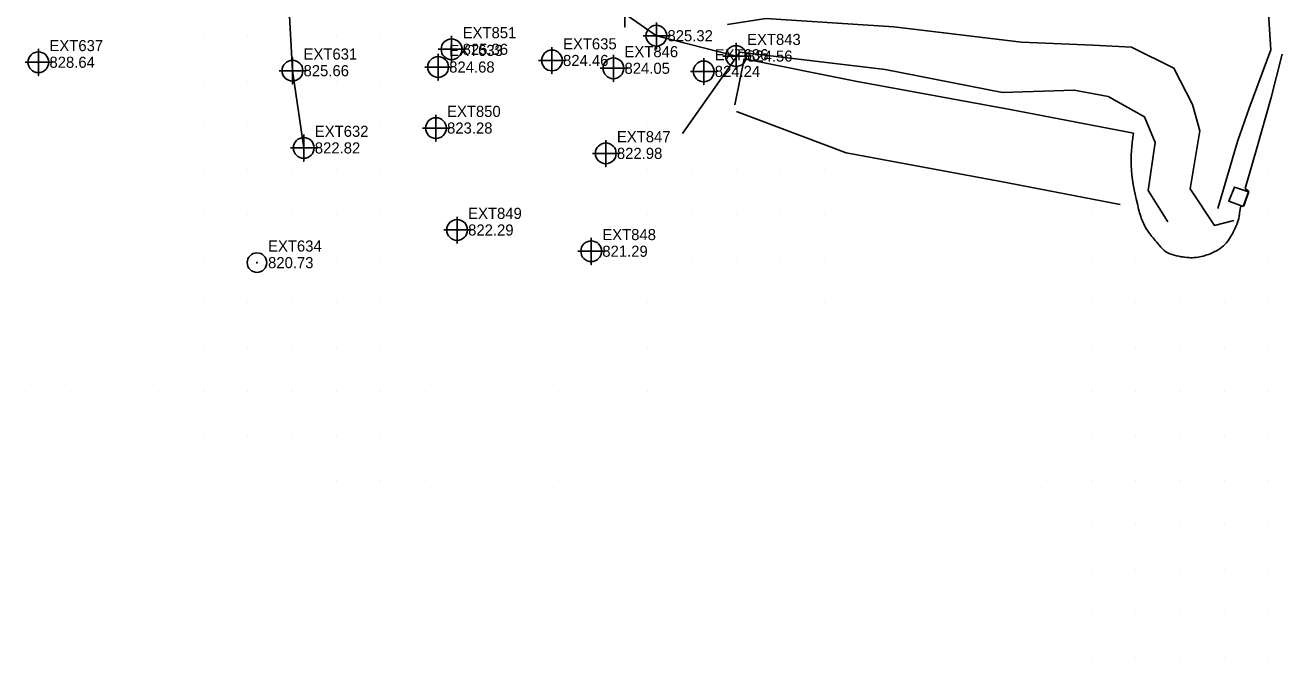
# Model space of a CAD drawing. Extents: x 1762120 to 1766775, y 709485 to 712965.
# Drawn here: x 1762809.9 to 1763091.8, y 712400 to 712542.6 of the extents above; entities that cross this region are included whole.
import ezdxf

# ---------------------------------------------------------------- set-up
doc = ezdxf.new("R2010")
doc.units = 0
for name, color, linetype in [('Exist DTM Breakline', 7, 'Continuous'), ('Exist DTM Breakline Cogo Elevation', 7, 'Continuous'), ('Exist DTM Breakline Cogo Number', 7, 'Continuous'), ('Exist DTM Breakline Cogo Point CELL', 7, 'Continuous'), ('Exist DTM QL2 LIDAR Elevation Point', 7, 'Continuous'), ('Exist DTM Regular Point CELL', 7, 'Continuous'), ('Exist DTM Regular Point Cogo Elevation', 7, 'Continuous'), ('Exist DTM Regular Point Cogo Number', 7, 'Continuous'), ('Exist Property Iron Pin CELL', 7, 'Continuous'), ('Exist Property Iron Pin Cogo Elevation', 7, 'Continuous'), ('Exist Property Iron Pin Cogo Number', 7, 'Continuous'), ('Exist Roads EOP', 7, 'Continuous'), ('Exist Roads EOP Other', 7, 'Continuous')]:
    doc.layers.add(name, color=color, linetype=linetype)

msp = doc.modelspace()

# ---------------------------------------------------------------- linework, layer by layer
at = {"layer": 'Exist DTM Breakline'}
for points in [[(1763078.51, 712501.3), (1763082.89, 712516.4), (1763085.56, 712523.9), (1763090.42, 712537.05), (1763089.79, 712546.34), (1763082.89, 712551.55), (1763067.24, 712555.92), (1763059.84, 712556.24), (1763056.72, 712558.52), (1763053.11, 712557.11), (1763041.81, 712560.64), (1763027.13, 712563.07), (1763013.63, 712566.46), (1762998, 712571.18), (1762987.84, 712574.31), (1762976.14, 712576.14), (1762969.55, 712578.67)], [(1762967.82, 712549.03), (1762948.14, 712552.08), (1762916.63, 712551.93), (1762895.25, 712554.12), (1762880.51, 712555.14), (1762869.37, 712546.08), (1762870.08, 712532.35), (1762872.62, 712514.94)], [(1762969.97, 712535.64), (1762952.03, 712540.23), (1762944.95, 712545.17)], [(1763082.1, 712498.57), (1763077.71, 712497.47), (1763072.23, 712505.75), (1763074.42, 712518.77), (1763072.8, 712524.74), (1763068.57, 712532.95), (1763059, 712537.64), (1763050.39, 712538.11), (1763034.3, 712538.76), (1763005.54, 712542.24), (1762976.69, 712544.08), (1762968.07, 712542.75), (1762968.07, 712542.75)], [(1762957.94, 712518.18), (1762970.82, 712536.53), (1763003.56, 712532.58), (1763029.97, 712527.47), (1763046.16, 712527.96), (1763053.81, 712526.52), (1763061.98, 712521.96), (1763064.38, 712516.19), (1763062.82, 712505.34), (1763067.21, 712498.31)], [(1762970.05, 712523.18), (1762994.75, 712513.87), (1763029.64, 712507.36), (1763056.49, 712502.17)]]:
    msp.add_lwpolyline(points, dxfattribs=at)
at = {"layer": 'Exist DTM Breakline Cogo Point CELL'}
for points in [[(1762944.95, 712548.17), (1762944.95, 712542.17), (1762944.95, 712545.17), (1762947.95, 712545.17), (1762941.95, 712545.17)], [(1762952.03, 712543.23), (1762952.03, 712537.23), (1762952.03, 712540.23), (1762955.03, 712540.23), (1762949.03, 712540.23)], [(1762969.97, 712538.64), (1762969.97, 712532.64), (1762969.97, 712535.64), (1762972.97, 712535.64), (1762966.97, 712535.64)], [(1762870.08, 712535.35), (1762870.08, 712529.35), (1762870.08, 712532.35), (1762873.08, 712532.35), (1762867.08, 712532.35)], [(1762872.62, 712517.94), (1762872.62, 712511.94), (1762872.62, 712514.94), (1762875.62, 712514.94), (1762869.62, 712514.94)]]:
    msp.add_lwpolyline(points, dxfattribs=at)
for centre in [(1762952.03, 712540.23), (1762969.97, 712535.64), (1762870.08, 712532.35), (1762872.62, 712514.94)]:
    msp.add_circle(centre, 2.34, dxfattribs=at)
at = {"layer": 'Exist DTM QL2 LIDAR Elevation Point'}
for p, q in [((1762810, 712540), (1762810, 712540)), ((1762820, 712540), (1762820, 712540)), ((1762830, 712540), (1762830, 712540)), ((1762840, 712540), (1762840, 712540)), ((1762850, 712540), (1762850, 712540)), ((1762860, 712540), (1762860, 712540)), ((1762880, 712540), (1762880, 712540)), ((1762890, 712540), (1762890, 712540)), ((1762900, 712540), (1762900, 712540)), ((1762810, 712530), (1762810, 712530)), ((1762820, 712530), (1762820, 712530)), ((1762830, 712530), (1762830, 712530)), ((1762840, 712530), (1762840, 712530)), ((1762850, 712530), (1762850, 712530)), ((1762860, 712530), (1762860, 712530)), ((1762880, 712530), (1762880, 712530)), ((1762890, 712530), (1762890, 712530)), ((1762900, 712530), (1762900, 712530)), ((1762810, 712520), (1762810, 712520)), ((1762820, 712520), (1762820, 712520)), ((1762830, 712520), (1762830, 712520)), ((1762840, 712520), (1762840, 712520)), ((1762850, 712520), (1762850, 712520)), ((1762860, 712520), (1762860, 712520)), ((1762880, 712520), (1762880, 712520)), ((1762890, 712520), (1762890, 712520)), ((1762950, 712520), (1762950, 712520)), ((1762810, 712510), (1762810, 712510)), ((1762820, 712510), (1762820, 712510)), ((1762830, 712510), (1762830, 712510)), ((1762840, 712510), (1762840, 712510)), ((1762850, 712510), (1762850, 712510)), ((1762860, 712510), (1762860, 712510)), ((1762870, 712510), (1762870, 712510)), ((1762880, 712510), (1762880, 712510)), ((1762890, 712510), (1762890, 712510)), ((1762950, 712510), (1762950, 712510)), ((1762960, 712510), (1762960, 712510)), ((1762970, 712510), (1762970, 712510)), ((1762980, 712510), (1762980, 712510)), ((1762990, 712510), (1762990, 712510)), ((1763090, 712510), (1763090, 712510)), ((1762810, 712500), (1762810, 712500)), ((1762820, 712500), (1762820, 712500)), ((1762830, 712500), (1762830, 712500)), ((1762840, 712500), (1762840, 712500)), ((1762850, 712500), (1762850, 712500)), ((1762860, 712500), (1762860, 712500)), ((1762870, 712500), (1762870, 712500)), ((1762880, 712500), (1762880, 712500)), ((1762890, 712500), (1762890, 712500)), ((1762950, 712500), (1762950, 712500)), ((1762960, 712500), (1762960, 712500)), ((1762970, 712500), (1762970, 712500)), ((1762980, 712500), (1762980, 712500)), ((1762990, 712500), (1762990, 712500)), ((1763000, 712500), (1763000, 712500)), ((1763010, 712500), (1763010, 712500)), ((1763020, 712500), (1763020, 712500)), ((1763030, 712500), (1763030, 712500)), ((1763040, 712500), (1763040, 712500)), ((1763050, 712500), (1763050, 712500)), ((1763090, 712500), (1763090, 712500)), ((1762810, 712490), (1762810, 712490)), ((1762820, 712490), (1762820, 712490)), ((1762830, 712490), (1762830, 712490)), ((1762840, 712490), (1762840, 712490)), ((1762850, 712490), (1762850, 712490)), ((1762860, 712490), (1762860, 712490)), ((1762870, 712490), (1762870, 712490)), ((1762880, 712490), (1762880, 712490)), ((1762890, 712490), (1762890, 712490)), ((1762950, 712490), (1762950, 712490)), ((1762960, 712490), (1762960, 712490)), ((1762970, 712490), (1762970, 712490)), ((1762980, 712490), (1762980, 712490)), ((1762990, 712490), (1762990, 712490)), ((1763000, 712490), (1763000, 712490)), ((1763010, 712490), (1763010, 712490)), ((1763020, 712490), (1763020, 712490)), ((1763030, 712490), (1763030, 712490)), ((1763040, 712490), (1763040, 712490)), ((1763050, 712490), (1763050, 712490)), ((1763060, 712490), (1763060, 712490)), ((1763090, 712490), (1763090, 712490)), ((1762810, 712480), (1762810, 712480)), ((1762820, 712480), (1762820, 712480)), ((1762830, 712480), (1762830, 712480)), ((1762840, 712480), (1762840, 712480)), ((1762850, 712480), (1762850, 712480)), ((1762860, 712480), (1762860, 712480)), ((1762870, 712480), (1762870, 712480)), ((1762880, 712480), (1762880, 712480)), ((1762890, 712480), (1762890, 712480)), ((1762900, 712480), (1762900, 712480)), ((1762910, 712480), (1762910, 712480)), ((1762920, 712480), (1762920, 712480)), ((1762930, 712480), (1762930, 712480)), ((1762940, 712480), (1762940, 712480)), ((1762950, 712480), (1762950, 712480)), ((1762990, 712480), (1762990, 712480)), ((1763000, 712480), (1763000, 712480)), ((1763010, 712480), (1763010, 712480)), ((1763020, 712480), (1763020, 712480)), ((1763030, 712480), (1763030, 712480)), ((1763040, 712480), (1763040, 712480)), ((1763050, 712480), (1763050, 712480)), ((1763060, 712480), (1763060, 712480)), ((1763070, 712480), (1763070, 712480)), ((1763080, 712480), (1763080, 712480)), ((1763090, 712480), (1763090, 712480)), ((1762810, 712470), (1762810, 712470)), ((1762820, 712470), (1762820, 712470)), ((1762830, 712470), (1762830, 712470)), ((1762840, 712470), (1762840, 712470)), ((1762850, 712470), (1762850, 712470)), ((1762860, 712470), (1762860, 712470)), ((1762870, 712470), (1762870, 712470)), ((1762880, 712470), (1762880, 712470)), ((1762890, 712470), (1762890, 712470)), ((1762900, 712470), (1762900, 712470)), ((1762910, 712470), (1762910, 712470)), ((1762920, 712470), (1762920, 712470)), ((1762930, 712470), (1762930, 712470)), ((1762940, 712470), (1762940, 712470)), ((1762950, 712470), (1762950, 712470)), ((1763030, 712470), (1763030, 712470)), ((1763040, 712470), (1763040, 712470)), ((1763050, 712470), (1763050, 712470)), ((1763060, 712470), (1763060, 712470)), ((1763070, 712470), (1763070, 712470)), ((1763080, 712470), (1763080, 712470)), ((1763090, 712470), (1763090, 712470)), ((1762810, 712460), (1762810, 712460)), ((1762820, 712460), (1762820, 712460)), ((1762830, 712460), (1762830, 712460)), ((1762840, 712460), (1762840, 712460)), ((1762850, 712460), (1762850, 712460)), ((1762860, 712460), (1762860, 712460)), ((1762870, 712460), (1762870, 712460)), ((1762880, 712460), (1762880, 712460)), ((1762890, 712460), (1762890, 712460)), ((1762900, 712460), (1762900, 712460)), ((1762910, 712460), (1762910, 712460)), ((1762920, 712460), (1762920, 712460)), ((1762930, 712460), (1762930, 712460)), ((1762940, 712460), (1762940, 712460)), ((1762950, 712460), (1762950, 712460)), ((1763050, 712460), (1763050, 712460)), ((1763060, 712460), (1763060, 712460)), ((1763070, 712460), (1763070, 712460)), ((1763080, 712460), (1763080, 712460)), ((1763090, 712460), (1763090, 712460)), ((1762840, 712450), (1762840, 712450)), ((1762850, 712450), (1762850, 712450)), ((1762860, 712450), (1762860, 712450)), ((1762870, 712450), (1762870, 712450)), ((1762880, 712450), (1762880, 712450)), ((1762890, 712450), (1762890, 712450)), ((1762900, 712450), (1762900, 712450)), ((1762910, 712450), (1762910, 712450)), ((1762920, 712450), (1762920, 712450)), ((1762930, 712450), (1762930, 712450)), ((1762940, 712450), (1762940, 712450)), ((1763040, 712450), (1763040, 712450)), ((1763050, 712450), (1763050, 712450)), ((1763060, 712450), (1763060, 712450)), ((1763070, 712450), (1763070, 712450)), ((1763080, 712450), (1763080, 712450)), ((1763090, 712450), (1763090, 712450)), ((1762880, 712440), (1762880, 712440)), ((1762890, 712440), (1762890, 712440)), ((1762900, 712440), (1762900, 712440)), ((1762910, 712440), (1762910, 712440)), ((1762920, 712440), (1762920, 712440)), ((1762930, 712440), (1762930, 712440)), ((1762940, 712440), (1762940, 712440)), ((1763040, 712440), (1763040, 712440)), ((1763050, 712440), (1763050, 712440)), ((1763060, 712440), (1763060, 712440)), ((1763070, 712440), (1763070, 712440)), ((1763080, 712440), (1763080, 712440)), ((1763090, 712440), (1763090, 712440)), ((1762930, 712430), (1762930, 712430)), ((1762940, 712430), (1762940, 712430)), ((1763040, 712430), (1763040, 712430)), ((1763050, 712430), (1763050, 712430)), ((1763060, 712430), (1763060, 712430)), ((1763070, 712430), (1763070, 712430)), ((1763080, 712430), (1763080, 712430)), ((1763090, 712430), (1763090, 712430)), ((1763040, 712420), (1763040, 712420)), ((1763050, 712420), (1763050, 712420)), ((1763060, 712420), (1763060, 712420)), ((1763070, 712420), (1763070, 712420)), ((1763080, 712420), (1763080, 712420)), ((1763090, 712420), (1763090, 712420)), ((1763040, 712410), (1763040, 712410)), ((1763050, 712410), (1763050, 712410)), ((1763060, 712410), (1763060, 712410)), ((1763070, 712410), (1763070, 712410)), ((1763080, 712410), (1763080, 712410)), ((1763090, 712410), (1763090, 712410)), ((1763040, 712400), (1763040, 712400)), ((1763050, 712400), (1763050, 712400)), ((1763060, 712400), (1763060, 712400)), ((1763070, 712400), (1763070, 712400)), ((1763080, 712400), (1763080, 712400)), ((1763090, 712400), (1763090, 712400))]:
    msp.add_line(p, q, dxfattribs=at)
at = {"layer": 'Exist DTM Regular Point CELL'}
for points in [[(1762905.91, 712540.17), (1762905.91, 712534.17), (1762905.91, 712537.17), (1762908.91, 712537.17), (1762902.91, 712537.17)], [(1762812.86, 712537.25), (1762812.86, 712531.25), (1762812.86, 712534.25), (1762815.86, 712534.25), (1762809.86, 712534.25)], [(1762902.88, 712536.17), (1762902.88, 712530.17), (1762902.88, 712533.17), (1762905.88, 712533.17), (1762899.88, 712533.17)], [(1762928.52, 712537.65), (1762928.52, 712531.65), (1762928.52, 712534.65), (1762931.52, 712534.65), (1762925.52, 712534.65)], [(1762942.36, 712535.89), (1762942.36, 712529.89), (1762942.36, 712532.89), (1762945.36, 712532.89), (1762939.36, 712532.89)], [(1762962.69, 712535.19), (1762962.69, 712529.19), (1762962.69, 712532.19), (1762965.69, 712532.19), (1762959.69, 712532.19)], [(1762902.4, 712522.42), (1762902.4, 712516.42), (1762902.4, 712519.42), (1762905.4, 712519.42), (1762899.4, 712519.42)], [(1762940.65, 712516.72), (1762940.65, 712510.72), (1762940.65, 712513.72), (1762943.65, 712513.72), (1762937.65, 712513.72)], [(1762907.15, 712499.45), (1762907.15, 712493.45), (1762907.15, 712496.45), (1762910.15, 712496.45), (1762904.15, 712496.45)], [(1762937.36, 712494.66), (1762937.36, 712488.66), (1762937.36, 712491.66), (1762940.36, 712491.66), (1762934.36, 712491.66)]]:
    msp.add_lwpolyline(points, dxfattribs=at)
for centre in [(1762905.91, 712537.17), (1762812.86, 712534.25), (1762902.88, 712533.17), (1762928.52, 712534.65), (1762942.36, 712532.89), (1762962.69, 712532.19), (1762902.4, 712519.42), (1762940.65, 712513.72), (1762907.15, 712496.45), (1762937.36, 712491.66)]:
    msp.add_circle(centre, 2.34, dxfattribs=at)
at = {"layer": 'Exist Property Iron Pin CELL'}
for radius in [2.2, 0.0707]:
    msp.add_circle((1762862.09, 712489.09), radius, dxfattribs=at)
at = {"layer": 'Exist Roads EOP'}
for points in [[(1763092.94, 712536.05), (1763090.46, 712526.31), (1763087.26, 712514.91), (1763084.6, 712505.83), (1763085.45, 712505.1), (1763084.3, 712501.85)], [(1763059.48, 712518.25), (1763031.71, 712523.61), (1762997.22, 712529.91), (1762971.79, 712535.01), (1762969.7, 712524.68)], [(1763083.69, 712501.86), (1763083.38, 712500.33)]]:
    msp.add_lwpolyline(points, dxfattribs=at)
msp.add_spline([(1763083.38, 712500.33), (1763083.28, 712499.47), (1763081.94, 712495.98), (1763080.14, 712493.24), (1763076.76, 712491.11), (1763073.6, 712490.25), (1763070.22, 712490.43), (1763066.39, 712491.83), (1763064.89, 712493.46), (1763062.94, 712495.88), (1763061.25, 712499.11), (1763060.35, 712502.37), (1763058.94, 712511.03), (1763059.09, 712515.06), (1763059.48, 712518.25)], degree=3, dxfattribs=at)
at = {"layer": 'Exist Roads EOP Other'}
msp.add_lwpolyline([(1763084.19, 712501.75), (1763085.36, 712505.03), (1763082.2, 712506.13), (1763080.98, 712502.91), (1763084.19, 712501.75)], dxfattribs=at)

# ---------------------------------------------------------------- texts
at = {"layer": 'Exist DTM Breakline Cogo Elevation'}
for s, p in [('825.32', (1762954.53, 712538.98)), ('824.56', (1762972.47, 712534.39)), ('825.66', (1762872.58, 712531.1)), ('822.82', (1762875.12, 712513.69))]:
    msp.add_text(s, height=2.5, dxfattribs=at).set_placement(p)
at = {"layer": 'Exist DTM Breakline Cogo Number'}
for s, p in [('EXT843', (1762972.47, 712538.14)), ('EXT631', (1762872.58, 712534.85)), ('EXT632', (1762875.12, 712517.44))]:
    msp.add_text(s, height=2.5, dxfattribs=at).set_placement(p)
at = {"layer": 'Exist DTM Regular Point Cogo Elevation'}
for s, p in [('825.36', (1762908.41, 712535.92)), ('828.64', (1762815.36, 712533)), ('824.46', (1762931.02, 712533.4)), ('824.68', (1762905.38, 712531.92)), ('824.05', (1762944.86, 712531.64)), ('824.24', (1762965.19, 712530.94)), ('823.28', (1762904.9, 712518.18)), ('822.98', (1762943.15, 712512.47)), ('822.29', (1762909.65, 712495.2)), ('821.29', (1762939.86, 712490.41))]:
    msp.add_text(s, height=2.5, dxfattribs=at).set_placement(p)
at = {"layer": 'Exist DTM Regular Point Cogo Number'}
for s, p in [('EXT851', (1762908.41, 712539.67)), ('EXT637', (1762815.36, 712536.75)), ('EXT633', (1762905.38, 712535.67)), ('EXT635', (1762931.02, 712537.15)), ('EXT846', (1762944.86, 712535.39)), ('EXT636', (1762965.19, 712534.69)), ('EXT850', (1762904.9, 712521.93)), ('EXT847', (1762943.15, 712516.22)), ('EXT849', (1762909.65, 712498.95)), ('EXT848', (1762939.86, 712494.16))]:
    msp.add_text(s, height=2.5, dxfattribs=at).set_placement(p)
at = {"layer": 'Exist Property Iron Pin Cogo Elevation'}
msp.add_text('820.73', height=2.5, dxfattribs=at).set_placement((1762864.59, 712487.84))
at = {"layer": 'Exist Property Iron Pin Cogo Number'}
msp.add_text('EXT634', height=2.5, dxfattribs=at).set_placement((1762864.59, 712491.59))

doc.saveas('drawing.dxf')
